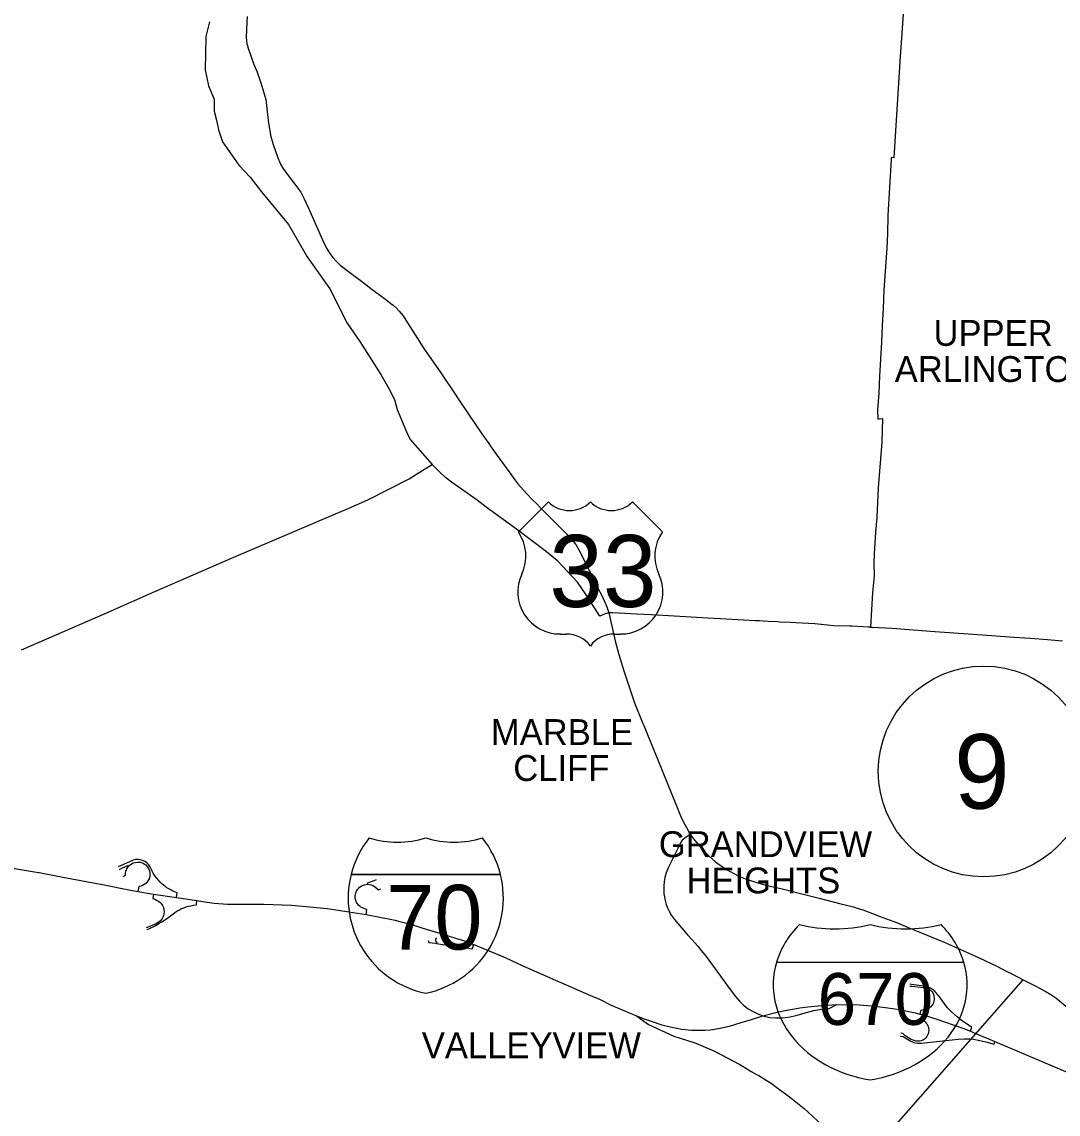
# Model space of a CAD drawing. Extents: x -1146 to -445, y -1283 to -822.
# Drawn here: x -959.3 to -909.3, y -1056.7 to -1003.9 of the extents above; entities that cross this region are included whole.
import ezdxf

# ---------------------------------------------------------------- set-up
doc = ezdxf.new("R2010")
doc.units = 0
for name, color, linetype in [('Default', 7, 'Continuous'), ('GM_X_Corporation_Text', 7, 'Continuous'), ('GM_X_Interchange_Ramps', 7, 'Continuous'), ('GM_X_Interstate_Route', 7, 'Continuous'), ('GM_X_Interstate_Shield', 7, 'Continuous'), ('GM_X_Township', 7, 'Continuous'), ('GM_X_US_Route', 7, 'Continuous'), ('GM_X_US_Shield', 7, 'Continuous')]:
    doc.layers.add(name, color=color, linetype=linetype)

msp = doc.modelspace()

# ---------------------------------------------------------------- linework, layer by layer
at = {"layer": 'Default'}
msp.add_lwpolyline([(-931.037, -1070.205), (-928.49, -1070.205), (-910.945, -1050.21)], dxfattribs=at)
msp.add_circle((-912.85, -1040.145), 5.094, dxfattribs=at)
at = {"layer": 'GM_X_Interchange_Ramps'}
for points in [[(-951.869, -1046.24), (-951.829, -1046.018), (-951.993, -1045.948), (-952.085, -1045.904), (-952.169, -1045.859), (-952.239, -1045.817), (-952.323, -1045.763), (-952.395, -1045.712), (-952.486, -1045.641), (-952.567, -1045.57), (-952.651, -1045.489), (-952.731, -1045.404), (-952.819, -1045.297), (-952.874, -1045.224), (-952.923, -1045.151), (-952.983, -1045.054), (-953.034, -1044.961), (-953.072, -1044.885), (-953.131, -1044.753), (-953.197, -1044.658), (-953.276, -1044.575), (-953.371, -1044.505), (-953.498, -1044.442), (-953.612, -1044.411), (-953.72, -1044.399), (-953.839, -1044.405), (-953.962, -1044.434), (-954.575, -1044.7), (-954.686, -1044.754)], [(-954.445, -1045.224), (-954.321, -1045.162), (-954.321, -1045.064), (-954.304, -1044.964), (-954.263, -1044.853), (-954.218, -1044.777), (-954.17, -1044.717), (-954.094, -1044.656), (-954.031, -1044.605), (-953.961, -1044.57), (-953.863, -1044.539), (-953.744, -1044.525), (-953.614, -1044.537), (-953.508, -1044.569), (-953.429, -1044.609), (-953.35, -1044.667), (-953.277, -1044.741), (-953.211, -1044.841), (-953.168, -1044.95), (-953.147, -1045.057), (-953.148, -1045.183), (-953.173, -1045.297), (-953.214, -1045.392), (-953.275, -1045.485), (-953.348, -1045.56), (-953.423, -1045.615), (-953.505, -1045.657), (-953.588, -1045.685), (-953.687, -1045.702), (-953.726, -1045.943)], [(-954.612, -1044.884), (-954.497, -1044.825), (-954.185, -1044.683), (-954.17, -1044.717)], [(-942.696, -1047.064), (-942.66, -1046.82), (-942.73, -1046.798), (-942.803, -1046.77), (-942.87, -1046.743), (-942.95, -1046.7), (-943.006, -1046.659), (-943.06, -1046.608), (-943.114, -1046.542), (-943.155, -1046.475), (-943.185, -1046.409), (-943.209, -1046.33), (-943.221, -1046.251), (-943.223, -1046.173), (-943.215, -1046.097), (-943.193, -1046.01), (-943.162, -1045.933), (-943.119, -1045.859), (-943.071, -1045.798), (-943.012, -1045.741), (-942.942, -1045.69), (-942.869, -1045.652), (-942.781, -1045.62), (-942.702, -1045.605), (-942.624, -1045.599), (-942.532, -1045.607), (-942.45, -1045.626), (-942.367, -1045.659), (-942.288, -1045.704), (-942.225, -1045.754), (-942.106, -1045.87), (-941.98, -1045.813)], [(-942.624, -1045.599), (-942.618, -1045.531), (-942.305, -1045.415), (-942.199, -1045.366)], [(-952.967, -1046.08), (-953.006, -1046.293), (-952.908, -1046.326), (-952.822, -1046.36), (-952.739, -1046.408), (-952.672, -1046.46), (-952.601, -1046.535), (-952.54, -1046.628), (-952.498, -1046.723), (-952.472, -1046.828), (-952.465, -1046.923), (-952.473, -1047.029), (-952.498, -1047.126), (-952.54, -1047.224), (-952.594, -1047.306), (-952.659, -1047.379), (-952.735, -1047.434), (-952.842, -1047.508), (-953.201, -1047.656), (-953.323, -1047.707)], [(-953.284, -1047.786), (-953.195, -1047.746), (-952.867, -1047.586), (-952.701, -1047.477), (-952.576, -1047.409), (-952.474, -1047.349), (-952.347, -1047.268), (-952.236, -1047.192), (-952.146, -1047.125), (-952.045, -1047.041), (-951.946, -1046.966), (-951.852, -1046.904), (-951.755, -1046.847), (-951.647, -1046.792), (-951.513, -1046.734), (-951.396, -1046.692), (-951.282, -1046.659), (-951.173, -1046.633), (-951.048, -1046.612), (-950.9, -1046.594), (-950.875, -1046.389)], [(-939.301, -1048.181), (-939.34, -1048.247), (-939.341, -1048.325), (-939.329, -1048.345), (-939.317, -1048.366), (-939.304, -1048.383), (-939.287, -1048.399), (-939.293, -1048.458)], [(-939.702, -1048.308), (-939.668, -1048.414), (-939.348, -1048.452), (-939.293, -1048.458), (-939.008, -1048.51), (-938.577, -1048.562), (-938.459, -1048.579), (-938.353, -1048.594), (-938.221, -1048.614), (-938.107, -1048.632), (-937.989, -1048.65), (-937.864, -1048.67), (-937.748, -1048.689), (-937.653, -1048.705), (-937.569, -1048.718), (-937.488, -1048.506)], [(-916.428, -1050.515), (-916.319, -1050.529), (-915.76, -1050.581), (-915.667, -1050.593), (-915.581, -1050.619), (-915.495, -1050.663), (-915.417, -1050.722), (-915.358, -1050.785), (-915.315, -1050.848), (-915.279, -1050.921), (-915.253, -1051.006), (-915.241, -1051.096), (-915.243, -1051.168), (-915.256, -1051.248), (-915.281, -1051.327), (-915.313, -1051.392), (-915.354, -1051.453), (-915.409, -1051.514), (-915.472, -1051.566), (-915.546, -1051.609), (-915.606, -1051.634), (-915.676, -1051.653), (-915.74, -1051.673), (-915.886, -1051.693), (-915.936, -1051.871)], [(-913.491, -1052.704), (-913.425, -1052.512), (-913.696, -1052.333), (-913.924, -1052.177), (-914.138, -1052.005), (-914.402, -1051.763), (-914.602, -1051.571), (-914.994, -1051.043), (-915.236, -1050.751), (-915.429, -1050.615), (-915.6, -1050.544), (-915.749, -1050.516), (-916.334, -1050.437), (-916.419, -1050.427)], [(-915.829, -1051.898), (-915.879, -1052.091), (-915.74, -1052.184), (-915.686, -1052.252), (-915.634, -1052.305), (-915.589, -1052.365), (-915.548, -1052.443), (-915.524, -1052.511), (-915.51, -1052.581), (-915.505, -1052.653), (-915.513, -1052.743), (-915.536, -1052.831), (-915.562, -1052.891), (-915.603, -1052.959), (-915.654, -1053.021), (-915.719, -1053.078), (-915.792, -1053.124), (-915.869, -1053.157), (-915.956, -1053.178), (-916.056, -1053.184), (-916.135, -1053.175), (-916.207, -1053.156), (-916.35, -1053.101), (-916.558, -1052.976), (-916.655, -1052.9), (-916.761, -1052.813), (-916.861, -1052.791)], [(-916.891, -1052.934), (-916.747, -1052.954), (-916.405, -1053.16), (-916.22, -1053.238), (-916.052, -1053.275), (-915.849, -1053.277), (-914.088, -1053.082), (-913.789, -1053.061), (-913.525, -1053.075), (-913.347, -1053.089), (-913.033, -1053.146), (-912.748, -1053.21), (-912.349, -1053.324), (-912.306, -1053.201)]]:
    msp.add_lwpolyline(points, dxfattribs=at)
at = {"layer": 'GM_X_Interstate_Route'}
for points in [[(-962.489, -1044.502), (-960.968, -1044.647), (-959.976, -1044.785), (-958.533, -1045.024), (-958.498, -1045.03)], [(-958.498, -1045.03), (-957.361, -1045.255), (-955.351, -1045.621), (-954.161, -1045.865)], [(-954.161, -1045.865), (-953.726, -1045.943), (-952.967, -1046.08), (-951.869, -1046.24), (-950.875, -1046.389), (-950.589, -1046.428)], [(-950.589, -1046.428), (-950.038, -1046.505), (-949.395, -1046.554), (-947.636, -1046.552), (-946.3, -1046.612), (-945.779, -1046.663), (-944.579, -1046.769), (-942.696, -1047.064), (-941.368, -1047.323)], [(-941.368, -1047.323), (-941.294, -1047.337), (-941.129, -1047.379)], [(-941.129, -1047.379), (-940.533, -1047.53)], [(-940.533, -1047.53), (-940.503, -1047.538), (-939.749, -1047.778), (-939.022, -1048), (-938.877, -1048.046), (-938.73, -1048.092), (-938.419, -1048.189)], [(-938.419, -1048.189), (-937.946, -1048.336), (-937.488, -1048.506), (-935.98, -1049.135), (-935.124, -1049.533), (-933.284, -1050.353), (-931.85, -1050.969)], [(-931.85, -1050.969), (-931.424, -1051.152), (-930.861, -1051.439), (-930.248, -1051.703), (-929.625, -1051.956)], [(-922.366, -1051.682), (-922.345, -1051.677), (-921.735, -1051.575), (-921.344, -1051.519), (-920.682, -1051.45), (-919.945, -1051.413)], [(-919.945, -1051.413), (-918.866, -1051.428), (-918.235, -1051.471), (-917.618, -1051.549), (-917.236, -1051.606), (-916.835, -1051.669), (-916.628, -1051.719), (-916.166, -1051.814), (-915.936, -1051.871), (-915.829, -1051.898), (-915.331, -1052.053)], [(-929.625, -1051.956), (-929.055, -1052.38), (-927.826, -1052.932), (-926.857, -1053.244), (-926.846, -1053.249)], [(-929.625, -1051.956), (-929.26, -1052.095), (-928.914, -1052.216), (-928.399, -1052.387), (-928.003, -1052.495), (-927.436, -1052.605), (-926.977, -1052.643), (-926.749, -1052.654), (-926.508, -1052.652), (-926.334, -1052.65), (-926.053, -1052.63), (-925.594, -1052.559), (-925.083, -1052.441), (-924.571, -1052.282)], [(-924.571, -1052.282), (-924.076, -1052.127), (-923.517, -1051.949), (-922.837, -1051.782), (-922.366, -1051.682)], [(-915.331, -1052.053), (-915.164, -1052.105), (-913.86, -1052.558), (-913.491, -1052.704), (-912.968, -1052.917), (-912.614, -1053.068), (-912.306, -1053.201), (-908.358, -1054.874), (-907.49, -1055.245), (-907.183, -1055.373), (-906.95, -1055.458), (-906.629, -1055.562), (-906.407, -1055.616), (-906.156, -1055.657), (-905.91, -1055.688), (-905.691, -1055.701), (-905.381, -1055.701), (-905.107, -1055.677), (-904.927, -1055.655), (-904.747, -1055.623), (-904.547, -1055.575), (-904.409, -1055.54), (-904.212, -1055.475)], [(-926.846, -1053.249), (-925.899, -1053.652), (-924.643, -1054.313), (-924.402, -1054.456)], [(-924.402, -1054.456), (-924.083, -1054.646), (-923.796, -1054.804), (-923.723, -1054.847)], [(-923.723, -1054.847), (-923.361, -1055.063), (-923.118, -1055.215), (-922.785, -1055.46), (-922.363, -1055.767), (-922.097, -1055.991), (-921.527, -1056.439), (-920.683, -1057.206), (-919.532, -1058.283), (-919.117, -1058.636), (-918.442, -1059.287), (-917.79, -1059.948), (-917.223, -1060.499), (-916.35, -1061.538), (-915.999, -1061.969), (-915.633, -1062.441)]]:
    msp.add_lwpolyline(points, dxfattribs=at)
at = {"layer": 'GM_X_Interstate_Shield'}
for p, q in [((-943.423, -1045.12), (-936.209, -1045.12)), ((-936.209, -1045.12), (-943.423, -1045.12)), ((-936.209, -1045.12), (-943.423, -1045.12)), ((-913.804, -1049.384), (-922.869, -1049.384)), ((-913.804, -1049.384), (-922.869, -1049.384))]:
    msp.add_line(p, q, dxfattribs=at)
for centre, start, end in [((-938.878, -1046.269), 141.669, 165.8066), ((-941.186, -1038.879), 253.0091, 286.9909), ((-938.446, -1038.879), 253.0091, 286.9909), ((-940.753, -1046.269), 14.1934, 38.331), ((-938.878, -1046.269), 165.8066, 258.463), ((-940.753, -1046.269), 281.537, 14.1934)]:
    msp.add_arc(centre, 4.688, start, end, dxfattribs=at)
for centre, start_param, end_param in [((-917.164, -1050.456), 2.47259, 2.911027), ((-920.048, -1043.065), 4.415841, 5.008937), ((-916.624, -1043.065), 4.415841, 5.008937), ((-919.508, -1050.456), 0.230566, 0.669003), ((-917.164, -1050.456), 2.911027, 4.511031), ((-919.508, -1050.456), 4.913747, 6.513751)]:
    msp.add_ellipse(centre, major_axis=(5.859, 0), ratio=0.8, start_param=start_param, end_param=end_param, dxfattribs=at)
at = {"layer": 'GM_X_Township'}
for points in [[(-916.732, -1003.331), (-916.907, -1005.839), (-917.201, -1010.494), (-917.318, -1010.478), (-917.318, -1010.577), (-917.477, -1013.283), (-917.504, -1014.171), (-917.535, -1014.861), (-917.671, -1016.881), (-917.713, -1017.775), (-917.752, -1018.598), (-917.789, -1019.409), (-917.836, -1020.226), (-917.879, -1021.045), (-917.917, -1021.859), (-917.989, -1022.671), (-917.973, -1023.101), (-917.903, -1023.099), (-917.737, -1023.095), (-917.78, -1024.228), (-917.957, -1026.439), (-918.016, -1027.877), (-918.086, -1028.605), (-918.147, -1029.621), (-918.159, -1030.087), (-918.14, -1030.691), (-918.229, -1031.503), (-918.326, -1033.178), (-918.436, -1033.172), (-919.215, -1033.133), (-919.321, -1033.127), (-920.096, -1033.108), (-921.016, -1033.017), (-921.924, -1032.965), (-922.205, -1032.954), (-922.724, -1032.934), (-922.812, -1032.924), (-923.274, -1032.899), (-923.501, -1032.887), (-923.68, -1032.872), (-923.906, -1032.862), (-924.453, -1032.836), (-925.564, -1032.776), (-926.18, -1032.734), (-927.534, -1032.655), (-928.913, -1032.579), (-929.611, -1032.539), (-930.771, -1032.475), (-930.974, -1032.486), (-931.149, -1032.531), (-931.405, -1032.648), (-932.066, -1031.61), (-932.489, -1030.992), (-933.433, -1029.983), (-933.986, -1029.527), (-935.431, -1028.432), (-936.897, -1027.38), (-937.336, -1027.042), (-938.576, -1026.165), (-938.864, -1025.939), (-939.14, -1025.689), (-939.512, -1025.31)], [(-950.272, -1003.919), (-950.445, -1004.625), (-950.479, -1006.243), (-950.324, -1007.017), (-950.048, -1007.654), (-950.048, -1008.24), (-949.928, -1008.67), (-949.825, -1009.135), (-949.635, -1009.72), (-948.843, -1010.856), (-948.31, -1011.424), (-947.759, -1012.13), (-946.45, -1013.713), (-945.555, -1015.271), (-944.453, -1016.82), (-943.61, -1018.49), (-943.007, -1019.368), (-941.991, -1020.968), (-941.595, -1021.64), (-941.32, -1022.173), (-941.199, -1022.655), (-940.754, -1023.736), (-940.568, -1024.098), (-939.512, -1025.31)], [(-959.353, -1034.273), (-955.306, -1032.509), (-952.911, -1031.453), (-949.099, -1029.791), (-944.294, -1027.738), (-943.568, -1027.434), (-942.609, -1027.014), (-940.614, -1026.004), (-939.962, -1025.594), (-939.512, -1025.31)], [(-909.041, -1033.846), (-909.769, -1033.787), (-910.594, -1033.72), (-911.389, -1033.675), (-912.677, -1033.58), (-915.207, -1033.393), (-916.235, -1033.327), (-917.275, -1033.243), (-918.245, -1033.183), (-918.326, -1033.178)], [(-918.326, -1033.178), (-918.245, -1033.183)]]:
    msp.add_lwpolyline(points, dxfattribs=at)
at = {"layer": 'GM_X_US_Route'}
for points in [[(-948.45, -1003.664), (-948.468, -1003.933), (-948.5, -1004.678), (-948.48, -1004.826), (-948.458, -1004.98), (-948.439, -1005.06), (-948.413, -1005.149), (-948.117, -1005.981), (-947.975, -1006.306), (-947.788, -1006.876), (-947.542, -1007.676), (-947.475, -1008.255), (-947.409, -1008.825), (-947.3, -1009.467), (-947.188, -1009.842), (-946.98, -1010.45), (-946.835, -1010.797), (-946.718, -1010.993), (-946.596, -1011.177), (-946.314, -1011.537), (-946.098, -1011.824), (-945.86, -1012.149), (-945.687, -1012.47), (-945.475, -1012.922), (-944.802, -1014.457), (-944.616, -1014.853), (-944.455, -1015.122), (-944.307, -1015.316), (-944.129, -1015.502), (-943.946, -1015.683), (-943.557, -1015.99), (-942.923, -1016.457), (-942.398, -1016.854), (-942.12, -1017.061), (-941.678, -1017.396), (-941.499, -1017.532)], [(-941.499, -1017.532), (-941.393, -1017.612), (-941.245, -1017.747), (-941.103, -1017.904), (-940.915, -1018.13), (-940.693, -1018.464), (-940.443, -1018.864)], [(-940.443, -1018.864), (-939.902, -1019.7), (-939.095, -1020.886), (-938.367, -1021.957)], [(-938.367, -1021.957), (-938.314, -1022.036), (-937.717, -1022.923), (-937.109, -1023.837)], [(-937.109, -1023.837), (-936.775, -1024.293), (-936.718, -1024.373)], [(-936.718, -1024.373), (-936.489, -1024.697), (-936.111, -1025.229), (-935.712, -1025.776), (-935.555, -1025.988)], [(-935.555, -1025.988), (-935.367, -1026.242), (-934.954, -1026.715), (-934.65, -1027.028), (-934.451, -1027.221), (-934.266, -1027.403), (-933.578, -1028.095), (-932.938, -1028.749), (-932.556, -1029.174), (-932.415, -1029.443), (-932.092, -1030.066), (-931.745, -1030.789), (-931.51, -1031.257), (-931.497, -1031.284)], [(-931.497, -1031.284), (-931.33, -1031.619), (-931.161, -1031.973), (-931.068, -1032.197), (-930.974, -1032.486), (-930.855, -1032.978), (-930.638, -1033.901), (-930.482, -1034.491), (-930.245, -1035.279), (-930.024, -1035.962), (-929.722, -1036.832), (-929.321, -1037.825), (-929.281, -1037.922)], [(-929.281, -1037.922), (-928.895, -1038.883), (-928.602, -1039.591), (-928.151, -1040.704), (-927.704, -1041.804), (-927.502, -1042.288), (-927.371, -1042.558), (-927.217, -1042.856), (-927.036, -1043.19)], [(-927.036, -1043.19), (-927.23, -1043.316), (-927.421, -1043.47), (-927.505, -1043.604), (-927.634, -1043.866)], [(-927.036, -1043.19), (-926.817, -1043.479), (-926.542, -1043.808), (-926.132, -1044.232), (-925.808, -1044.507), (-925.428, -1044.781), (-925.253, -1044.896), (-925.11, -1044.98), (-924.964, -1045.065), (-924.691, -1045.204), (-924.37, -1045.336), (-924.077, -1045.436), (-923.762, -1045.534), (-923.308, -1045.651), (-922.662, -1045.809), (-921.646, -1046.059), (-920.797, -1046.274), (-919.751, -1046.539), (-919.268, -1046.654), (-918.692, -1046.836), (-918.102, -1047.052), (-917.897, -1047.132), (-917.191, -1047.398), (-917.019, -1047.47), (-916.388, -1047.728), (-916.284, -1047.768)], [(-927.634, -1043.866), (-927.745, -1044.09), (-928.087, -1044.772), (-928.191, -1045.043), (-928.254, -1045.267), (-928.289, -1045.484), (-928.313, -1045.677), (-928.315, -1045.903), (-928.304, -1046.065), (-928.282, -1046.207), (-928.263, -1046.326), (-928.23, -1046.454), (-928.193, -1046.58), (-928.133, -1046.734), (-928.059, -1046.894), (-927.944, -1047.101), (-927.796, -1047.309), (-927.54, -1047.6), (-927.169, -1048.042), (-926.94, -1048.287), (-926.659, -1048.596), (-926.484, -1048.812)], [(-916.284, -1047.768), (-916.171, -1047.812)], [(-916.171, -1047.812), (-914.76, -1048.403), (-914.031, -1048.715), (-913.072, -1049.159), (-912.191, -1049.579), (-911.77, -1049.79)], [(-926.484, -1048.812), (-926.257, -1049.091), (-925.574, -1050.039), (-925.203, -1050.547), (-924.851, -1051.015), (-924.649, -1051.25), (-924.467, -1051.436), (-924.228, -1051.612), (-923.992, -1051.749), (-923.901, -1051.799), (-923.803, -1051.845), (-923.517, -1051.949), (-923.187, -1052.029), (-922.918, -1052.059), (-922.748, -1052.059), (-922.555, -1052.055), (-922.206, -1052.003), (-921.937, -1051.944), (-921.414, -1051.795), (-921.056, -1051.706), (-920.774, -1051.656), (-920.353, -1051.614), (-919.945, -1051.413)], [(-911.77, -1049.79), (-911.453, -1049.948), (-910.945, -1050.21), (-910.37, -1050.503), (-909.884, -1050.762), (-909.602, -1050.927), (-909.365, -1051.087), (-909.183, -1051.228), (-908.873, -1051.489), (-908.567, -1051.764), (-908.271, -1052.022), (-908.271, -1052.022)]]:
    msp.add_lwpolyline(points, dxfattribs=at)
at = {"layer": 'GM_X_US_Shield'}
for p, q in [((-933.891, -1027.124), (-935.341, -1028.574)), ((-928.38, -1028.574), (-929.83, -1027.124)), ((-933.311, -1033.505), (-933.021, -1033.505)), ((-930.7, -1033.505), (-930.41, -1033.505))]:
    msp.add_line(p, q, dxfattribs=at)
for centre, radius, start, end in [((-932.876, -1026.088), 1.45, 225.573, 314.427), ((-930.846, -1026.088), 1.45, 225.573, 314.427), ((-937.004, -1029.738), 2.03, 334.5471, 35.0009), ((-926.717, -1029.738), 2.03, 144.9991, 205.4529), ((-933.333, -1031.474), 2.03, 154.8319, 270.6383), ((-930.388, -1031.474), 2.03, 269.3617, 25.1681), ((-933.021, -1034.955), 1.45, 36.8699, 90), ((-930.7, -1034.955), 1.45, 90, 143.1301)]:
    msp.add_arc(centre, radius, start, end, dxfattribs=at)

# ---------------------------------------------------------------- texts
at = {"layer": 'Default'}
msp.add_text('9', height=3.6, dxfattribs=at).set_placement((-914.278, -1041.945))
at = {"layer": 'GM_X_Corporation_Text'}
for s, p in [('UPPER', (-915.276, -1019.58)), ('ARLINGTON', (-917.151, -1021.327)), ('MARBLE', (-936.67, -1038.87)), ('CLIFF', (-935.587, -1040.605)), ('GRANDVIEW', (-928.551, -1044.288)), ('HEIGHTS', (-927.214, -1046.039)), ('VALLEYVIEW', (-940.006, -1054.009))]:
    msp.add_text(s, height=1.25, rotation=0, dxfattribs=at).set_placement(p)
at = {"layer": 'GM_X_Interstate_Shield'}
for s, height, p in [('70', 3.125, (-941.722, -1048.753)), ('670', 2.5, (-920.877, -1052.392))]:
    msp.add_text(s, height=height, dxfattribs=at).set_placement(p)
at = {"layer": 'GM_X_US_Shield'}
msp.add_text('33', height=3.4805, dxfattribs=at).set_placement((-933.842, -1032.199))

doc.saveas('drawing.dxf')
